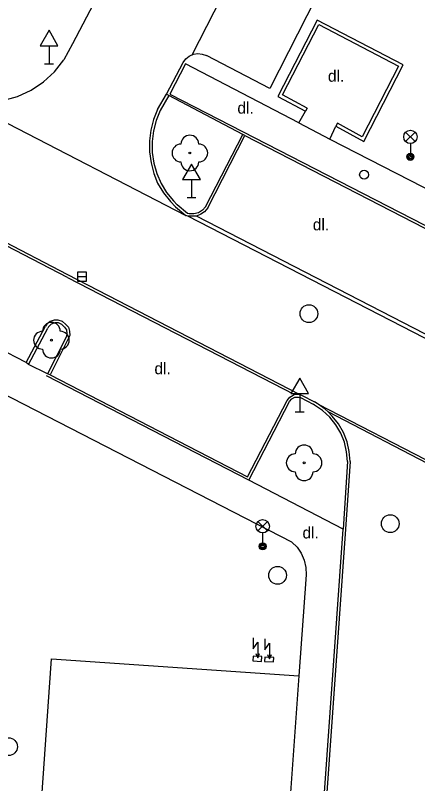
# Model space of a CAD drawing. Extents: x -539515 to -538098, y -1182060 to -1180157.
# Drawn here: x -538386.9 to -538364.3, y -1181460.29 to -1181417.12 of the extents above; entities that cross this region are included whole.
import ezdxf

# ---------------------------------------------------------------- set-up
doc = ezdxf.new("R2010")
doc.units = 0
for name, color, linetype in [('Vrstva 10', 7, 'Continuous'), ('Vrstva 11', 7, 'Continuous'), ('Vrstva 22', 7, 'Continuous'), ('Vrstva 24', 7, 'Continuous'), ('Vrstva 27', 7, 'Continuous'), ('Vrstva 28', 7, 'Continuous'), ('Vrstva 33', 7, 'Continuous'), ('Vrstva 34', 7, 'Continuous'), ('Vrstva 40', 7, 'Continuous'), ('Vrstva 5', 7, 'Continuous'), ('Vrstva 7', 7, 'Continuous')]:
    doc.layers.add(name, color=color, linetype=linetype)

msp = doc.modelspace()

# ---------------------------------------------------------------- linework, layer by layer
at = {"layer": 'Vrstva 10'}
for p, q in [((-538376.965, -1181419.335), (-538364.399, -1181394.744)), ((-538374.44, -1181401.04), (-538383.7, -1181418.72)), ((-538366.95, -1181410.09), (-538372.61, -1181421.23)), ((-538383.7, -1181418.72), (-538384.18, -1181419.62)), ((-538372.61, -1181421.23), (-538376.17, -1181419.38)), ((-538390.11, -1181421.76), (-538377.33, -1181428.36)), ((-538378.277, -1181421.62), (-538378.776, -1181422.465)), ((-538376.213, -1181427.867), (-538374.133, -1181423.807)), ((-538376.09, -1181427.93), (-538374.01, -1181423.87)), ((-538374.01, -1181423.87), (-538362.91, -1181429.58)), ((-538383.95, -1181431.69), (-538394.39, -1181426.31)), ((-538383.98, -1181431.84), (-538394.117, -1181426.624)), ((-538377.91, -1181427.88), (-538377.33, -1181428.36)), ((-538377.235, -1181428.245), (-538377.807, -1181427.772)), ((-538353.55, -1181440.61), (-538377.22, -1181428.392)), ((-538353.897, -1181440.162), (-538376.735, -1181428.392)), ((-538386.3, -1181436.63), (-538396.11, -1181431.6)), ((-538383.98, -1181431.84), (-538371.22, -1181438.43)), ((-538370.937, -1181438.424), (-538383.95, -1181431.69)), ((-538384.04, -1181435.16), (-538385.091, -1181437.252)), ((-538383.84, -1181435.11), (-538384.95, -1181437.32)), ((-538384.95, -1181437.32), (-538373.86, -1181443.05)), ((-538373.86, -1181443.05), (-538371.63, -1181438.75)), ((-538373.79, -1181443.24), (-538371.497, -1181438.819)), ((-538370.89, -1181438.592), (-538370.17, -1181438.972)), ((-538370.82, -1181438.46), (-538370.1, -1181438.84)), ((-538369.893, -1181438.963), (-538355.66, -1181446.33)), ((-538356.334, -1181446.147), (-538369.333, -1181439.397)), ((-538368.239, -1181442.183), (-538368.48, -1181445.99)), ((-538368.09, -1181442.18), (-538368.35, -1181445.99)), ((-538368.35, -1181445.99), (-538370.43, -1181475.29))]:
    msp.add_line(p, q, dxfattribs=at)
for points in [[(-538377.48, -1181419.76), (-538377.328, -1181419.561), (-538377.131, -1181419.407), (-538377.02, -1181419.35), (-538376.965, -1181419.335), (-538376.901, -1181419.307), (-538376.654, -1181419.268), (-538376.405, -1181419.293), (-538376.17, -1181419.38)], [(-538390.11, -1181421.76), (-538389.285, -1181421.941), (-538388.443, -1181421.989), (-538387.603, -1181421.9), (-538386.788, -1181421.678), (-538386.02, -1181421.329), (-538385.317, -1181420.861), (-538384.699, -1181420.286), (-538384.18, -1181419.62)], [(-538378.91, -1181422.4), (-538378.41, -1181421.55), (-538377.48, -1181419.76)], [(-538374.01, -1181423.87), (-538374.133, -1181423.807), (-538378.277, -1181421.62), (-538378.41, -1181421.55)], [(-538378.91, -1181422.4), (-538379.14, -1181422.971), (-538379.294, -1181423.566), (-538379.37, -1181424.177), (-538379.366, -1181424.792), (-538379.28, -1181425.41), (-538379.12, -1181425.995), (-538378.91, -1181426.55), (-538378.573, -1181427.094), (-538378.197, -1181427.581), (-538377.91, -1181427.88)], [(-538378.776, -1181422.465), (-538379.001, -1181423.026), (-538379.151, -1181423.613), (-538379.222, -1181424.214), (-538379.214, -1181424.82), (-538379.126, -1181425.419), (-538378.959, -1181426.001), (-538378.718, -1181426.556), (-538378.405, -1181427.074), (-538378.027, -1181427.547), (-538377.807, -1181427.772)], [(-538376.09, -1181427.93), (-538376.276, -1181428.151), (-538376.49, -1181428.28), (-538376.735, -1181428.392), (-538376.79, -1181428.404), (-538377.11, -1181428.4), (-538377.22, -1181428.392), (-538377.33, -1181428.36)], [(-538376.213, -1181427.867), (-538376.383, -1181428.061), (-538376.61, -1181428.205), (-538376.87, -1181428.276), (-538377.139, -1181428.268), (-538377.235, -1181428.245)], [(-538384.08, -1181434.46), (-538384.266, -1181434.314), (-538384.491, -1181434.237), (-538384.728, -1181434.24), (-538384.951, -1181434.32), (-538385.135, -1181434.469), (-538385.22, -1181434.59)], [(-538384.148, -1181434.635), (-538384.294, -1181434.486), (-538384.485, -1181434.403), (-538384.692, -1181434.398), (-538384.887, -1181434.47), (-538385.041, -1181434.61), (-538385.09, -1181434.69)], [(-538384.08, -1181434.46), (-538383.927, -1181434.629), (-538383.86, -1181434.86), (-538383.84, -1181435.11)], [(-538386.17, -1181436.73), (-538386.3, -1181436.63), (-538385.22, -1181434.59)], [(-538384.95, -1181437.32), (-538385.091, -1181437.252), (-538386.17, -1181436.73), (-538385.09, -1181434.69)], [(-538384.148, -1181434.635), (-538384.039, -1181434.796), (-538384.004, -1181434.986), (-538384.04, -1181435.16)], [(-538371.63, -1181438.75), (-538371.491, -1181438.573), (-538371.299, -1181438.455), (-538371.22, -1181438.43), (-538371.078, -1181438.411), (-538370.937, -1181438.424), (-538370.83, -1181438.45), (-538370.82, -1181438.46)], [(-538371.497, -1181438.819), (-538371.372, -1181438.669), (-538371.197, -1181438.579), (-538371, -1181438.565), (-538370.89, -1181438.592)], [(-538368.239, -1181442.183), (-538368.29, -1181441.637), (-538368.419, -1181441.105), (-538368.625, -1181440.597), (-538368.902, -1181440.124), (-538369.244, -1181439.697), (-538369.646, -1181439.324), (-538370.097, -1181439.014), (-538370.17, -1181438.972)], [(-538368.09, -1181442.18), (-538368.141, -1181441.624), (-538368.27, -1181441.08), (-538368.476, -1181440.561), (-538368.754, -1181440.076), (-538369.098, -1181439.636), (-538369.333, -1181439.397), (-538369.501, -1181439.249), (-538369.893, -1181438.963), (-538369.955, -1181438.924), (-538370.1, -1181438.84)]]:
    msp.add_lwpolyline(points, dxfattribs=at)
at = {"layer": 'Vrstva 11'}
for p, q in [((-538377.35, -1181419.85), (-538378.23, -1181421.54)), ((-538370.98, -1181423.16), (-538377.35, -1181419.85)), ((-538378.23, -1181421.54), (-538362.71, -1181429.53)), ((-538370.98, -1181423.16), (-538370.6, -1181422.5)), ((-538370.98, -1181423.16), (-538369.24, -1181424.07)), ((-538369.24, -1181424.07), (-538368.89, -1181423.35)), ((-538369.24, -1181424.07), (-538348.75, -1181434.59)), ((-538373.79, -1181443.24), (-538385.15, -1181437.37)), ((-538368.48, -1181445.99), (-538373.79, -1181443.24)), ((-538370.56, -1181475.283), (-538368.48, -1181445.99)), ((-538370.56, -1181448.56), (-538370.97, -1181454.23))]:
    msp.add_line(p, q, dxfattribs=at)
for points in [[(-538371.38, -1181446.71), (-538391.67, -1181436.28), (-538393.51, -1181435.36)], [(-538371.38, -1181446.71), (-538371.079, -1181447.002), (-538370.84, -1181447.345), (-538370.67, -1181447.728), (-538370.575, -1181448.136), (-538370.56, -1181448.56)]]:
    msp.add_lwpolyline(points, dxfattribs=at)
at = {"layer": 'Vrstva 22'}
for centre in [(-538377.1, -1181424.85), (-538384.88, -1181435.37), (-538370.68, -1181442.26)]:
    msp.add_circle(centre, 0.05, dxfattribs=at)
for centre, start, end in [((-538377.1, -1181424.35), 0, 180), ((-538377.6, -1181424.85), 90, 270), ((-538376.6, -1181424.85), 270, 90), ((-538377.1, -1181425.35), 180, 0), ((-538384.88, -1181434.87), 0, 180), ((-538385.38, -1181435.37), 90, 270), ((-538384.38, -1181435.37), 270, 90), ((-538384.88, -1181435.87), 180, 0), ((-538370.68, -1181441.76), 0, 180), ((-538371.18, -1181442.26), 90, 270), ((-538370.18, -1181442.26), 270, 90), ((-538370.68, -1181442.76), 180, 0)]:
    msp.add_arc(centre, 0.5, start, end, dxfattribs=at)
at = {"layer": 'Vrstva 24'}
for p, q in [((-538373.54, -1181452.094), (-538373.54, -1181452.72)), ((-538372.88, -1181452.144), (-538372.88, -1181452.77)), ((-538373.54, -1181452.72), (-538373.29, -1181452.345)), ((-538373.29, -1181452.345), (-538373.29, -1181453.22)), ((-538372.88, -1181452.77), (-538372.63, -1181452.395)), ((-538372.63, -1181452.395), (-538372.63, -1181453.27)), ((-538373.4, -1181452.975), (-538373.29, -1181453.22)), ((-538373.29, -1181453.22), (-538373.18, -1181452.975)), ((-538372.74, -1181453.025), (-538372.63, -1181453.27)), ((-538372.63, -1181453.27), (-538372.52, -1181453.025))]:
    msp.add_line(p, q, dxfattribs=at)
for points in [[(-538373.54, -1181453.12), (-538373.557, -1181453.392), (-538373.067, -1181453.422), (-538373.05, -1181453.15), (-538373.54, -1181453.12)], [(-538372.89, -1181453.18), (-538372.9, -1181453.429), (-538372.4, -1181453.449), (-538372.39, -1181453.2), (-538372.89, -1181453.18)]]:
    msp.add_lwpolyline(points, dxfattribs=at)
at = {"layer": 'Vrstva 27'}
msp.add_line((-538383.41, -1181431.8), (-538382.91, -1181431.8), dxfattribs=at)
msp.add_lwpolyline([(-538383.41, -1181432.05), (-538382.91, -1181432.05), (-538382.91, -1181431.55), (-538383.41, -1181431.55)], close=True, dxfattribs=at)
for centre in [(-538370.41, -1181433.88), (-538365.84, -1181445.68), (-538372.17, -1181448.58), (-538387.29, -1181458.21)]:
    msp.add_circle(centre, 0.5, dxfattribs=at)
at = {"layer": 'Vrstva 28'}
msp.add_circle((-538367.31, -1181426.07), 0.25, dxfattribs=at)
at = {"layer": 'Vrstva 33'}
for p, q in [((-538364.975, -1181424.21), (-538364.445, -1181423.68)), ((-538364.975, -1181423.68), (-538364.445, -1181424.21)), ((-538364.71, -1181424.32), (-538364.71, -1181425.07)), ((-538373.275, -1181446.09), (-538372.745, -1181445.56)), ((-538373.275, -1181445.56), (-538372.745, -1181446.09)), ((-538373.01, -1181446.2), (-538373.01, -1181446.95))]:
    msp.add_line(p, q, dxfattribs=at)
for centre, radius in [((-538364.71, -1181423.945), 0.375), ((-538364.71, -1181425.07), 0.2), ((-538364.71, -1181425.07), 0.145), ((-538364.71, -1181425.07), 0.0876), ((-538373.01, -1181445.825), 0.375), ((-538373.01, -1181446.95), 0.2), ((-538373.01, -1181446.95), 0.145), ((-538373.01, -1181446.95), 0.0876)]:
    msp.add_circle(centre, radius, dxfattribs=at)
at = {"layer": 'Vrstva 34'}
for p, q in [((-538385.01, -1181418.824), (-538385.01, -1181419.84)), ((-538385.26, -1181419.84), (-538384.76, -1181419.84)), ((-538377.01, -1181426.344), (-538377.01, -1181427.36)), ((-538377.26, -1181427.36), (-538376.76, -1181427.36)), ((-538370.93, -1181438.372), (-538370.93, -1181439.39)), ((-538371.18, -1181439.39), (-538370.68, -1181439.39))]:
    msp.add_line(p, q, dxfattribs=at)
for points in [[(-538385.51, -1181418.824), (-538384.51, -1181418.824), (-538385.01, -1181417.956)], [(-538377.51, -1181426.344), (-538376.51, -1181426.344), (-538377.01, -1181425.476)], [(-538371.43, -1181438.372), (-538370.43, -1181438.372), (-538370.93, -1181437.506)]]:
    msp.add_lwpolyline(points, close=True, dxfattribs=at)
at = {"layer": 'Vrstva 5'}
for p, q in [((-538386.3, -1181473.8), (-538384.87, -1181453.27)), ((-538384.87, -1181453.27), (-538370.97, -1181454.23)), ((-538370.97, -1181454.23), (-538371.61, -1181463.19))]:
    msp.add_line(p, q, dxfattribs=at)
at = {"layer": 'Vrstva 7'}
for p, q in [((-538365.12, -1181419.89), (-538369.94, -1181417.38)), ((-538369.859, -1181417.637), (-538365.375, -1181419.972)), ((-538370.51, -1181422.333), (-538370.6, -1181422.5)), ((-538368.798, -1181423.184), (-538368.89, -1181423.35))]:
    msp.add_line(p, q, dxfattribs=at)
for points in [[(-538369.94, -1181417.38), (-538372.15, -1181421.67), (-538370.6, -1181422.5)], [(-538370.51, -1181422.333), (-538371.896, -1181421.591), (-538369.859, -1181417.637)], [(-538368.89, -1181423.35), (-538367.33, -1181424.21), (-538365.12, -1181419.89)], [(-538365.375, -1181419.972), (-538367.41, -1181423.949), (-538368.798, -1181423.184)]]:
    msp.add_lwpolyline(points, dxfattribs=at)

# ---------------------------------------------------------------- texts
at = {"layer": 'Vrstva 40'}
for p in [(-538369.342, -1181420.845), (-538374.43, -1181422.64), (-538370.191, -1181429.196), (-538379.091, -1181437.281), (-538370.772, -1181446.511)]:
    msp.add_text('dl.', height=0.65, dxfattribs=at).set_placement(p)

doc.saveas('drawing.dxf')
